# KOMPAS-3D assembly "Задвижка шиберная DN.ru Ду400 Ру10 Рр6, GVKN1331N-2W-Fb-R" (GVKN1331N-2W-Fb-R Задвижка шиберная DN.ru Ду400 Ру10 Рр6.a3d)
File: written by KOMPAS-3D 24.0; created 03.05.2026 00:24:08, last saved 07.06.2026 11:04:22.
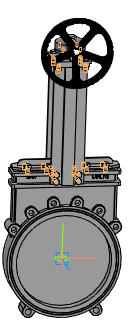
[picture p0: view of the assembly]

Document properties: Автор: DN.ru; Полное имя файла: E:\Работа\Зайцев\АУТСОРС\Даня\GVKN1331N-2W-Fb-R Задвижка шиберная DN.ru Ду400-600 Ру4-6\исходные материалы\DN400\GVKN1331N-2W-Fb-R Задвижка шиберная DN.ru Ду400 Ру10 Рр6.a3d

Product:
- Component [detail]: 1  | qty 1  | pos. 1  | Масса: 18.2; Раздел спецификации: Прочие изделия; Примечание: D050-23732; Автор: R2D2; source file: GVKN1331N-2W-Fb-R Задвижка шиберная DN.ru Ду400 Ру10 Рр6.m3d
- Component [detail]: Деталь 2  | qty 1  | pos. 2  | Масса: 4.081657; Автор: mrdid; additional columns: Типовые; source file: Деталь 2 - Деталь 2.m3d
- Part/product: Задвижка шиберная DN.ru Ду400 Ру10 Рр6  | designation GVKN1331N-2W-Fb-R
    Масса: 90
    Раздел спецификации: Прочие изделия
    Примечание: D040-07578

Referenced files in E:\Работа\Зайцев\АУТСОРС\Даня\GVKN1331N-2W-Fb-R Задвижка шиберная DN.ru Ду400-600 Ру4-6\исходные материалы\DN400\: Деталь 2 - Деталь 2.m3d, GVKN1331N-2W-Fb-R Задвижка шиберная DN.ru Ду400 Ру10 Рр6.m3d
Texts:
  GVKN1331N-2W-Fb-R
  Деталь 2 Деталь 2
